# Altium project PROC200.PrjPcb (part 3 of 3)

## Sheet PROC200_EVM_Hardware.SchDoc
size 431 x 279 mm; Date: Not shown in title block; ApprovedBy: Not shown in title block; CheckedBy: Not shown in title block; Author: Not shown in title block; CompanyName: Not shown in title block; Engineer: Not shown in title block; Organization: Not shown in title block; Address1: Not shown in title block; Address2: Not shown in title block; Address3: Not shown in title block; Address4: Not shown in title block; DocumentNumber: 9; Revision: Use project parameter SCH_Rev; SheetNumber: 14; SheetTotal: 14; PageSetup: Record=PageOptions¦CenterHorizontal=True¦CenterVertical=True¦PrintScale=1.00¦XCorrection=1.00¦YCorrection=1.00¦PrintKind=0¦BorderSize=5000000¦LeftOffset=0¦BottomOffset=0¦Orientation=2¦PaperLength=1000¦PaperWidth=1000¦Scale=100¦PaperSource=15¦PrintQuality=600¦MediaType=1¦DitherType=10¦PaperKind=Letter¦PrintScaleMode=1
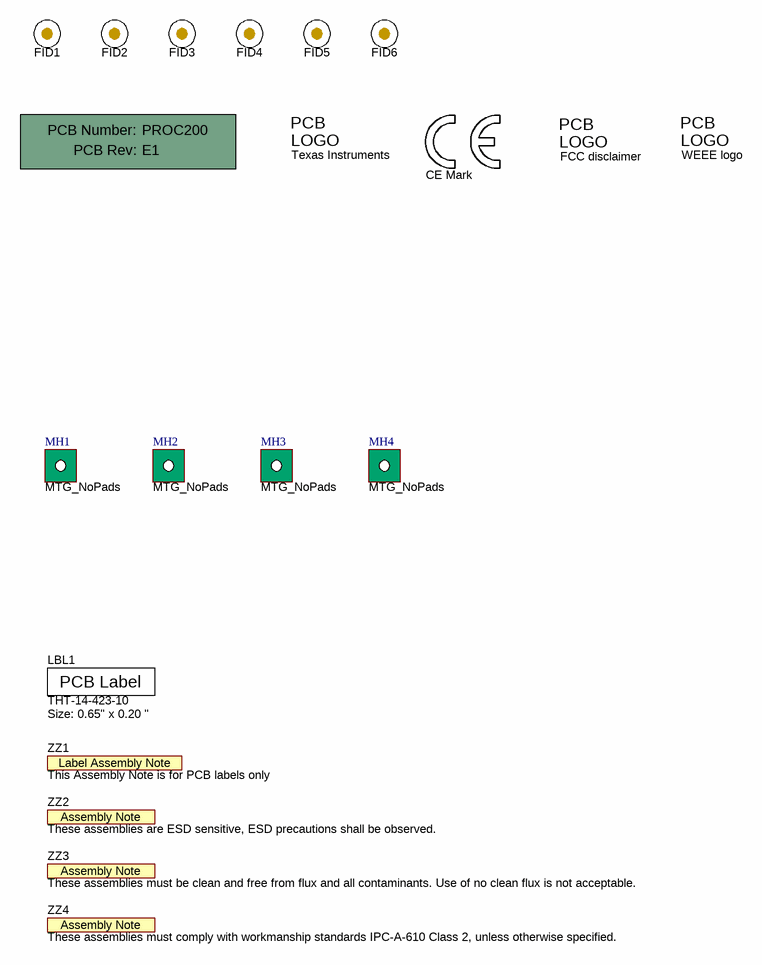
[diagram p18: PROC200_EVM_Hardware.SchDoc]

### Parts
!PCB1  Printed Circuit Board  (value not drawn)  (mechanical)
FID1  Fiducial  [Fiducial10-20]  (value not drawn)
FID2  Fiducial  [Fiducial10-20]  (value not drawn)
FID3  Fiducial  [Fiducial10-20]  (value not drawn)
FID4  Fiducial  [Fiducial10-20]  (value not drawn)
FID5  Fiducial  [Fiducial10-20]  (value not drawn)
FID6  Fiducial  [Fiducial10-20]  (value not drawn)
LBL1  THT-14-423-10  Note: Size: 0.65" x 0.20 "  [Label_650x200]
Logo1  CE Mark  [CE_Mark_5mm]  (no BOM)
Logo2  Texas Instruments  [TI_Stacked_Overlay_Small]  (no BOM)
Logo3  FCC disclaimer  [FCC_disclaimer]  (no BOM)
Logo4  WEEE logo  [WEEE_Minimum]  (no BOM)
MH1  MTG_NoPads  [MTG_159mil]  (no BOM)
MH2  MTG_NoPads  [MTG_159mil]  (no BOM)
MH3  MTG_NoPads  [MTG_159mil]  (no BOM)
MH4  MTG_NoPads  [MTG_159mil]  (no BOM)
ZZ1  This Assembly Note is for PCB labels only  [AssemblyNoteLabel]  (no BOM)
ZZ2  These assemblies are ESD sensitive, ESD precautions shall be observed.  [AssemblyNote]  (no BOM)
ZZ3  These assemblies must be clean and free from flux and all contaminants. Use of no clean flux is not acceptable.  [AssemblyNote]  (no BOM)
ZZ4  These assemblies must comply with workmanship standards IPC-A-610 Class 2, unless otherwise specified.  [AssemblyNote]  (no BOM)

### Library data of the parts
!PCB1 = CMP-0003618-2: Manufacturer: Any; PartNumber: PROC200
FID1-FID6 = CMP-0077181-1: Fiducial mark.  There is nothing to buy or mount.
LBL1 = CMP-0003625-1: Thermal Transfer Printable Labels, 0.650" W x 0.200" H - 10,000 per roll; Manufacturer: Brady
Logo1 = CMP-0074844-1: SymbolCreator: a0412235
Logo2 = CMP-0074838-1: Texas Instrument Corporate Signature; SymbolCreator: a0412235; Lib Reference: TI_Logo; Library Reference: Logo
Logo3 = CMP-0074847-1: FCC_disclaimer
Logo4 = CMP-0074769-3: Manufacturer: Texas Instruments; AEC Category: Q200; CompType: IC
MH1-MH4 = CMP-0078424-2: PCB Mounting Hole, No Pad; Manufacturer: Any; Key: Mounting Hole (non-standard) No Pad
ZZ1 = CMP-0003616-3
ZZ2 = CMP-0077236-1
ZZ3 = CMP-0077237-1
ZZ4 = CMP-0077238-1

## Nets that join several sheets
3V3_LDO2: PROC200_LDO_USB_MICRO-AB (6 pins), PROC200_OSPI_FSI _DAC_Emmulator_Header (12 pins), PROC200_PHY_MUX (31 pins), PROC200_RGMII1_PHY1 (5 pins), PROC200_MII0_PHY2 (5 pins), PROC200_MII1_ADD_ON_CONN (R79.1 R80.1), PROC200_High_Density_conn1_2 (J1.28), PROC200_HSEC_ADC (10 pins), PROC200_180pin_Edge_Connector (C27.2 C28.1 EC1.119 TP2.1)
5V0_LDO3: PROC200_High_Density_conn1_2 (J1.34), PROC200_180pin_Edge_Connector (C29.2 C30.1 EC1.117 TP3.1)
GND: PROC200_LDO_USB_MICRO-AB (32 pins), PROC200_OSPI_FSI _DAC_Emmulator_Header (21 pins), PROC200_PHY_MUX (18 pins), PROC200_RGMII1_PHY1 (33 pins), PROC200_MII0_PHY2 (33 pins), PROC200_MII1_ADD_ON_CONN (23 pins), PROC200_RJ45_1_2 (12 pins), PROC200_High_Density_conn1_2 (19 pins), PROC200_High_Density_conn3 (8 pins), PROC200_HSEC_ADC (29 pins), PROC200_180pin_Edge_Connector (27 pins)
SHIELD5: PROC200_LDO_USB_MICRO-AB (8 pins), PROC200_MII1_ADD_ON_CONN (6 pins)
VDD_ETH_1V1: PROC200_LDO_USB_MICRO-AB (C100.1 TP14.1 U12.1), PROC200_RGMII1_PHY1 (FB3.1), PROC200_MII0_PHY2 (FB1.1)
VDD_ETH_2V5: PROC200_LDO_USB_MICRO-AB (7 pins), PROC200_RGMII1_PHY1 (FB4.1), PROC200_MII0_PHY2 (FB2.1), PROC200_MII1_ADD_ON_CONN (C57.2 C58.1 J6.4 J6.6)
VDDIO_3V3: PROC200_LDO_USB_MICRO-AB (C76.1 R132.2 TP21.1 U11.6), PROC200_RGMII1_PHY1 (17 pins), PROC200_MII0_PHY2 (17 pins), PROC200_MII1_ADD_ON_CONN (C59.2 C60.1 J6.44 J6.46), PROC200_RJ45_1_2 (8 pins)
VMAIN_5V0_IN: PROC200_LDO_USB_MICRO-AB (6 pins), PROC200_High_Density_conn1_2 (J1.18 J1.20 R42.1), PROC200_High_Density_conn3 (J3.27), PROC200_180pin_Edge_Connector (9 pins)
AM26x_ADC0_AIN0/DAC_OUT: PROC200_High_Density_conn1_2 (J1.119), PROC200_HSEC_ADC (R134.1)
AM26x_ADC0_AIN1: PROC200_High_Density_conn1_2 (J1.117), PROC200_HSEC_ADC (R135.1)
AM26x_ADC0_AIN2_P: PROC200_High_Density_conn1_2 (J1.120), PROC200_HSEC_ADC (R136.1)
AM26x_ADC0_AIN3_N: PROC200_High_Density_conn1_2 (J1.118), PROC200_HSEC_ADC (R137.1)
AM26x_ADC0_AIN4_P: PROC200_High_Density_conn1_2 (J1.115), PROC200_HSEC_ADC (R138.1)
AM26x_ADC0_AIN5_N: PROC200_High_Density_conn1_2 (J1.113), PROC200_HSEC_ADC (R139.1)
AM26x_ADC1_AIN0_P: PROC200_High_Density_conn1_2 (J1.116), PROC200_HSEC_ADC (R140.1)
AM26x_ADC1_AIN1_N: PROC200_High_Density_conn1_2 (J1.114), PROC200_HSEC_ADC (R141.1)
AM26x_ADC1_AIN2_P: PROC200_High_Density_conn1_2 (J1.111), PROC200_HSEC_ADC (R142.1)
AM26x_ADC1_AIN3_N: PROC200_High_Density_conn1_2 (J1.109), PROC200_HSEC_ADC (R143.1)
AM26x_ADC1_AIN4: PROC200_High_Density_conn1_2 (J1.112), PROC200_HSEC_ADC (R144.1)
AM26x_ADC1_AIN5: PROC200_High_Density_conn1_2 (J1.110), PROC200_HSEC_ADC (R145.1)
AM26x_ADC2_AIN0_P: PROC200_High_Density_conn1_2 (J1.107), PROC200_HSEC_ADC (R146.1)
AM26x_ADC2_AIN1_N: PROC200_High_Density_conn1_2 (J1.105), PROC200_HSEC_ADC (R147.1)
AM26x_ADC2_AIN2_P: PROC200_High_Density_conn1_2 (J1.108), PROC200_HSEC_ADC (R148.1)
AM26x_ADC2_AIN3_N: PROC200_High_Density_conn1_2 (J1.106), PROC200_HSEC_ADC (R149.1)
AM26x_ADC2_AIN4: PROC200_High_Density_conn1_2 (J1.103), PROC200_HSEC_ADC (R150.1)
AM26x_ADC2_AIN5: PROC200_High_Density_conn1_2 (J1.101), PROC200_HSEC_ADC (R151.1)
AM26x_ADC_CAL0: PROC200_High_Density_conn1_2 (J1.92), PROC200_HSEC_ADC (R152.1)
AM26x_EPWM0_A: PROC200_High_Density_conn1_2 (J1.15), PROC200_180pin_Edge_Connector (EC1.49)
AM26x_EPWM0_B: PROC200_High_Density_conn1_2 (J1.13), PROC200_180pin_Edge_Connector (EC1.51)
AM26x_EPWM1_A: PROC200_High_Density_conn1_2 (J1.11), PROC200_180pin_Edge_Connector (EC1.53)
AM26x_EPWM1_B: PROC200_High_Density_conn1_2 (J1.9), PROC200_180pin_Edge_Connector (EC1.55)
AM26x_EPWM2_A: PROC200_High_Density_conn1_2 (J1.7), PROC200_180pin_Edge_Connector (EC1.50)
AM26x_EPWM2_B: PROC200_High_Density_conn1_2 (J1.5), PROC200_180pin_Edge_Connector (EC1.52)
AM26x_EPWM3_A: PROC200_High_Density_conn1_2 (J1.3), PROC200_180pin_Edge_Connector (EC1.54)
AM26x_EPWM3_B: PROC200_High_Density_conn1_2 (J1.1), PROC200_180pin_Edge_Connector (EC1.56)
AM26x_EPWM4_A: PROC200_High_Density_conn1_2 (J1.16), PROC200_180pin_Edge_Connector (EC1.57)
AM26x_EPWM4_B: PROC200_High_Density_conn1_2 (J1.14), PROC200_180pin_Edge_Connector (EC1.59)
AM26x_EPWM5_A: PROC200_High_Density_conn1_2 (J1.12), PROC200_180pin_Edge_Connector (EC1.61)
AM26x_EPWM5_B: PROC200_High_Density_conn1_2 (J1.10), PROC200_180pin_Edge_Connector (EC1.63)
AM26x_EPWM6_A: PROC200_High_Density_conn1_2 (J1.8), PROC200_180pin_Edge_Connector (EC1.58)
AM26x_EPWM6_B: PROC200_High_Density_conn1_2 (J1.6), PROC200_180pin_Edge_Connector (EC1.60)
AM26x_EPWM7_A: PROC200_OSPI_FSI _DAC_Emmulator_Header (R31.2), PROC200_High_Density_conn1_2 (J1.4), PROC200_180pin_Edge_Connector (EC1.62)
AM26x_EPWM7_B: PROC200_High_Density_conn1_2 (J1.2), PROC200_180pin_Edge_Connector (EC1.64)
AM26x_EPWM8_A: PROC200_High_Density_conn1_2 (J2.58), PROC200_180pin_Edge_Connector (EC2.159)
AM26x_EPWM8_B: PROC200_High_Density_conn1_2 (J2.60), PROC200_180pin_Edge_Connector (EC2.161)
AM26x_EPWM9_A: PROC200_High_Density_conn1_2 (J2.54), PROC200_180pin_Edge_Connector (EC2.163)
AM26x_EPWM9_B: PROC200_High_Density_conn1_2 (J2.56), PROC200_180pin_Edge_Connector (EC2.165)
AM26x_EQEP0_A: PROC200_High_Density_conn1_2 (J1.71), PROC200_180pin_Edge_Connector (EC1.100)
AM26x_EQEP0_B: PROC200_High_Density_conn1_2 (J1.69), PROC200_180pin_Edge_Connector (EC1.102)
AM26x_EQEP0_INDEX: PROC200_High_Density_conn1_2 (J1.65), PROC200_180pin_Edge_Connector (EC1.106)
AM26x_EQEP0_STROBE: PROC200_High_Density_conn1_2 (J1.67), PROC200_180pin_Edge_Connector (EC1.104)
AM26x_FSITX0_CLK: PROC200_OSPI_FSI _DAC_Emmulator_Header (J8.7), PROC200_High_Density_conn1_2 (J1.49)
AM26x_FSITX0_DATA0: PROC200_OSPI_FSI _DAC_Emmulator_Header (J8.5), PROC200_High_Density_conn1_2 (J1.53)
AM26x_FSITX0_DATA1: PROC200_OSPI_FSI _DAC_Emmulator_Header (J8.6), PROC200_High_Density_conn1_2 (J1.51)
AM26x_GPIO15: PROC200_High_Density_conn3 (J3.57), PROC200_180pin_Edge_Connector (EC1.81)
AM26x_GPIO81: PROC200_High_Density_conn3 (J3.72), PROC200_180pin_Edge_Connector (EC1.96)
AM26x_I2C2_SCL: PROC200_High_Density_conn1_2 (J1.61), PROC200_180pin_Edge_Connector (EC1.87)
AM26x_I2C2_SDA: PROC200_High_Density_conn1_2 (J1.63), PROC200_180pin_Edge_Connector (EC1.85)
AM26x_LIN1_RXD: PROC200_High_Density_conn1_2 (J1.37), PROC200_180pin_Edge_Connector (EC1.76)
AM26x_LIN1_TXD: PROC200_High_Density_conn1_2 (J1.35), PROC200_180pin_Edge_Connector (EC1.78)
AM26x_MCAN0_RX: PROC200_High_Density_conn1_2 (J1.38), PROC200_180pin_Edge_Connector (EC1.80)
AM26x_MCAN0_TX: PROC200_High_Density_conn1_2 (J1.36), PROC200_180pin_Edge_Connector (EC1.82)
AM26x_MCAN1_RX: PROC200_High_Density_conn3 (J3.56), PROC200_180pin_Edge_Connector (EC1.94)
AM26x_MCAN1_TX: PROC200_High_Density_conn3 (J3.54), PROC200_180pin_Edge_Connector (EC1.95)
AM26x_SDFM0_CLK0: PROC200_High_Density_conn1_2 (J1.54), PROC200_180pin_Edge_Connector (EC1.72)
AM26x_SDFM0_CLK3: PROC200_High_Density_conn1_2 (J1.46), PROC200_180pin_Edge_Connector (EC1.109)
AM26x_SDFM0_D0: PROC200_High_Density_conn1_2 (J1.60), PROC200_180pin_Edge_Connector (EC1.91)
AM26x_SDFM0_D1: PROC200_High_Density_conn1_2 (J1.58), PROC200_180pin_Edge_Connector (EC1.99)
AM26x_SDFM0_D2: PROC200_High_Density_conn1_2 (J1.56), PROC200_180pin_Edge_Connector (EC1.103)
AM26x_SDFM0_D3: PROC200_High_Density_conn1_2 (J1.50), PROC200_180pin_Edge_Connector (EC1.107)
AM26x_SPI0_CLK: PROC200_High_Density_conn1_2 (J2.34), PROC200_180pin_Edge_Connector (EC1.71)
AM26x_SPI0_CS0: PROC200_High_Density_conn1_2 (J2.36), PROC200_180pin_Edge_Connector (EC1.73)
AM26x_SPI0_D0: PROC200_High_Density_conn1_2 (J2.32), PROC200_180pin_Edge_Connector (EC1.69)
AM26x_SPI0_D1: PROC200_High_Density_conn1_2 (J2.30), PROC200_180pin_Edge_Connector (EC1.67)
AM26x_SPI3_CLK: PROC200_OSPI_FSI _DAC_Emmulator_Header (J4.13), PROC200_High_Density_conn1_2 (J1.41), PROC200_180pin_Edge_Connector (EC2.168)
AM26x_SPI3_CS0: PROC200_OSPI_FSI _DAC_Emmulator_Header (J4.16), PROC200_High_Density_conn1_2 (J1.39), PROC200_180pin_Edge_Connector (EC2.170)
AM26x_SPI3_D0: PROC200_OSPI_FSI _DAC_Emmulator_Header (J4.14), PROC200_High_Density_conn1_2 (J1.45), PROC200_180pin_Edge_Connector (EC2.164)
AM26x_SPI3_D1: PROC200_OSPI_FSI _DAC_Emmulator_Header (J4.15), PROC200_High_Density_conn1_2 (J1.43), PROC200_180pin_Edge_Connector (EC2.166)
AM26x_UART0_RXD: PROC200_OSPI_FSI _DAC_Emmulator_Header (J4.9), PROC200_High_Density_conn1_2 (J1.33), PROC200_180pin_Edge_Connector (EC1.86)
AM26x_UART0_TXD: PROC200_OSPI_FSI _DAC_Emmulator_Header (J4.10), PROC200_High_Density_conn1_2 (J1.31), PROC200_180pin_Edge_Connector (EC1.88)
AM26x_USB0_DM: PROC200_LDO_USB_MICRO-AB (L1.3 R92.1 R93.1), PROC200_High_Density_conn1_2 (J2.40)
AM26x_USB0_DP: PROC200_LDO_USB_MICRO-AB (L1.2 R90.1 R92.2), PROC200_High_Density_conn1_2 (J2.38)
AM26x_USB0_DRVVBUS: PROC200_LDO_USB_MICRO-AB (SW1.1), PROC200_High_Density_conn1_2 (J2.26)
AM26x_VREFHI1: PROC200_High_Density_conn1_2 (J1.85), PROC200_180pin_Edge_Connector (R154.2 R155.1 TP18.1)
AM26x_VREFLO: PROC200_High_Density_conn1_2 (J1.87), PROC200_180pin_Edge_Connector (EC1.43)
DAC_TCK: PROC200_High_Density_conn1_2 (J1.22 R158.2), PROC200_180pin_Edge_Connector (EC1.5)
DAC_TDI: PROC200_High_Density_conn1_2 (J1.19 R156.2), PROC200_180pin_Edge_Connector (EC1.8)
DAC_TDO: PROC200_High_Density_conn1_2 (J1.21 R157.2), PROC200_180pin_Edge_Connector (EC1.6)
DAC_TMS: PROC200_High_Density_conn1_2 (J1.24 R161.2), PROC200_180pin_Edge_Connector (EC1.3)
EXT_VMON2: PROC200_MII1_ADD_ON_CONN (J6.2 TP11.1), PROC200_High_Density_conn3 (J3.59)
HDR_DAC_TCK: PROC200_OSPI_FSI _DAC_Emmulator_Header (J4.4), PROC200_High_Density_conn1_2 (R158.1)
HDR_DAC_TDI: PROC200_OSPI_FSI _DAC_Emmulator_Header (J4.5), PROC200_High_Density_conn1_2 (R156.1)
HDR_DAC_TDO: PROC200_OSPI_FSI _DAC_Emmulator_Header (J4.6), PROC200_High_Density_conn1_2 (R157.1)
HDR_DAC_TMS: PROC200_OSPI_FSI _DAC_Emmulator_Header (J4.3), PROC200_High_Density_conn1_2 (R161.1)
HDR_FSIRX0_CLK: PROC200_OSPI_FSI _DAC_Emmulator_Header (J8.3), PROC200_High_Density_conn1_2 (R39.1)
HDR_FSIRX0_DATA0: PROC200_OSPI_FSI _DAC_Emmulator_Header (J8.1), PROC200_High_Density_conn1_2 (R126.1)
HDR_FSIRX0_DATA1: PROC200_OSPI_FSI _DAC_Emmulator_Header (J8.2), PROC200_High_Density_conn1_2 (R41.1)
HSEC_ADC0_AIN0/DAC_OUT: PROC200_HSEC_ADC (C79.2 R134.2 U3.1), PROC200_180pin_Edge_Connector (EC1.9)
HSEC_ADC0_AIN1: PROC200_HSEC_ADC (C62.2 R135.2 U3.2), PROC200_180pin_Edge_Connector (EC1.11)
HSEC_ADC0_AIN2_P: PROC200_HSEC_ADC (C80.2 R136.2 U3.5), PROC200_180pin_Edge_Connector (EC1.15)
HSEC_ADC0_AIN3_N: PROC200_HSEC_ADC (C63.2 R137.2 U3.4), PROC200_180pin_Edge_Connector (EC1.17)
HSEC_ADC0_AIN4_P: PROC200_HSEC_ADC (C81.2 R138.2 U4.2), PROC200_180pin_Edge_Connector (EC1.21)
HSEC_ADC0_AIN5_N: PROC200_HSEC_ADC (C64.2 R139.2 U4.1), PROC200_180pin_Edge_Connector (EC1.23)
HSEC_ADC1_AIN0_P: PROC200_HSEC_ADC (C82.2 R140.2 U4.4), PROC200_180pin_Edge_Connector (EC1.12)
HSEC_ADC1_AIN1_N: PROC200_HSEC_ADC (C65.2 R141.2 U4.5), PROC200_180pin_Edge_Connector (EC1.14)
HSEC_ADC1_AIN2_P: PROC200_HSEC_ADC (C83.2 R142.2 U5.1), PROC200_180pin_Edge_Connector (EC1.18)
HSEC_ADC1_AIN3_N: PROC200_HSEC_ADC (C66.2 R143.2 U5.2), PROC200_180pin_Edge_Connector (EC1.20)
HSEC_ADC1_AIN4: PROC200_HSEC_ADC (C84.2 R144.2 U6.1), PROC200_180pin_Edge_Connector (EC1.24)
HSEC_ADC1_AIN5: PROC200_HSEC_ADC (C67.2 R145.2 U6.2), PROC200_180pin_Edge_Connector (EC1.26)
HSEC_ADC2_AIN0_P: PROC200_HSEC_ADC (C85.2 R146.2 U6.5), PROC200_180pin_Edge_Connector (EC1.25)
HSEC_ADC2_AIN1_N: PROC200_HSEC_ADC (C68.2 R147.2 U6.4), PROC200_180pin_Edge_Connector (EC1.27)
HSEC_ADC2_AIN2_P: PROC200_HSEC_ADC (C86.2 R148.2 U5.5), PROC200_180pin_Edge_Connector (EC1.31)
HSEC_ADC2_AIN3_N: PROC200_HSEC_ADC (C69.2 R149.2 U5.4), PROC200_180pin_Edge_Connector (EC1.33)
HSEC_ADC2_AIN4: PROC200_HSEC_ADC (C87.2 R150.2 U7.1), PROC200_180pin_Edge_Connector (EC1.37)
HSEC_ADC2_AIN5: PROC200_HSEC_ADC (C70.2 R151.2 U7.2), PROC200_180pin_Edge_Connector (EC1.39)
HSEC_ADC_CAL0: PROC200_HSEC_ADC (C94.2 R152.2 U7.4), PROC200_180pin_Edge_Connector (EC1.28)
HSEC_FSIRX0_CLK: PROC200_High_Density_conn1_2 (R40.1), PROC200_180pin_Edge_Connector (EC1.79)
HSEC_FSIRX0_DATA0: PROC200_High_Density_conn1_2 (R127.1), PROC200_180pin_Edge_Connector (EC1.75)
HSEC_FSIRX0_DATA1: PROC200_High_Density_conn1_2 (R125.1), PROC200_180pin_Edge_Connector (EC1.77)
HSEC_ICSSM_MII0_COL: PROC200_PHY_MUX (U16.24), PROC200_180pin_Edge_Connector (EC1.110)
HSEC_ICSSM_MII0_CRS: PROC200_PHY_MUX (U16.22), PROC200_180pin_Edge_Connector (EC2.121)
HSEC_ICSSM_MII0_RX_DV: PROC200_PHY_MUX (U16.33), PROC200_180pin_Edge_Connector (EC2.124)
HSEC_ICSSM_MII0_RXCLK: PROC200_PHY_MUX (U16.28), PROC200_180pin_Edge_Connector (EC2.123)
HSEC_ICSSM_MII0_RXD0: PROC200_PHY_MUX (U16.42), PROC200_180pin_Edge_Connector (EC2.125)
HSEC_ICSSM_MII0_RXD1: PROC200_PHY_MUX (U16.40), PROC200_180pin_Edge_Connector (EC2.126)
HSEC_ICSSM_MII0_RXD2: PROC200_PHY_MUX (U16.37), PROC200_180pin_Edge_Connector (EC2.127)
HSEC_ICSSM_MII0_RXD3: PROC200_PHY_MUX (U16.35), PROC200_180pin_Edge_Connector (EC2.128)
HSEC_ICSSM_MII0_RXER: PROC200_PHY_MUX (U16.31), PROC200_180pin_Edge_Connector (EC1.108)
HSEC_ICSSM_MII0_RXLINK: PROC200_PHY_MUX (U16.26), PROC200_180pin_Edge_Connector (EC2.122)
HSEC_ICSSM_MII0_TXCLK: PROC200_PHY_MUX (U18.40), PROC200_180pin_Edge_Connector (EC2.129)
HSEC_ICSSM_MII0_TXD0: PROC200_PHY_MUX (U18.37), PROC200_180pin_Edge_Connector (EC2.131)
HSEC_ICSSM_MII0_TXD1: PROC200_PHY_MUX (U18.35), PROC200_180pin_Edge_Connector (EC2.132)
HSEC_ICSSM_MII0_TXD2: PROC200_PHY_MUX (U18.33), PROC200_180pin_Edge_Connector (EC2.133)
HSEC_ICSSM_MII0_TXD3: PROC200_PHY_MUX (U18.31), PROC200_180pin_Edge_Connector (EC2.134)
HSEC_ICSSM_MII0_TXEN: PROC200_PHY_MUX (U18.42), PROC200_180pin_Edge_Connector (EC2.130)
HSEC_ICSSM_MII1_COL: PROC200_PHY_MUX (U17.24), PROC200_180pin_Edge_Connector (EC2.138)
HSEC_ICSSM_MII1_CRS: PROC200_PHY_MUX (U17.22), PROC200_180pin_Edge_Connector (EC2.139)
HSEC_ICSSM_MII1_RX_DV: PROC200_PHY_MUX (U17.33), PROC200_180pin_Edge_Connector (EC2.142)
HSEC_ICSSM_MII1_RXCLK: PROC200_PHY_MUX (U17.28), PROC200_180pin_Edge_Connector (EC2.141)
HSEC_ICSSM_MII1_RXD0: PROC200_PHY_MUX (U17.42), PROC200_180pin_Edge_Connector (EC2.143)
HSEC_ICSSM_MII1_RXD1: PROC200_PHY_MUX (U17.40), PROC200_180pin_Edge_Connector (EC2.144)
HSEC_ICSSM_MII1_RXD2: PROC200_PHY_MUX (U17.37), PROC200_180pin_Edge_Connector (EC2.145)
HSEC_ICSSM_MII1_RXD3: PROC200_PHY_MUX (U17.35), PROC200_180pin_Edge_Connector (EC2.146)
HSEC_ICSSM_MII1_RXER: PROC200_PHY_MUX (U17.31), PROC200_180pin_Edge_Connector (EC2.137)
HSEC_ICSSM_MII1_RXLINK: PROC200_PHY_MUX (U17.26), PROC200_180pin_Edge_Connector (EC2.140)
HSEC_ICSSM_MII1_TXCLK: PROC200_PHY_MUX (U18.18), PROC200_180pin_Edge_Connector (EC2.147)
HSEC_ICSSM_MII1_TXD0: PROC200_PHY_MUX (U18.28), PROC200_180pin_Edge_Connector (EC2.149)
HSEC_ICSSM_MII1_TXD1: PROC200_PHY_MUX (U18.26), PROC200_180pin_Edge_Connector (EC2.150)
HSEC_ICSSM_MII1_TXD2: PROC200_PHY_MUX (U18.24), PROC200_180pin_Edge_Connector (EC2.151)
HSEC_ICSSM_MII1_TXD3: PROC200_PHY_MUX (U18.22), PROC200_180pin_Edge_Connector (EC2.152)
HSEC_ICSSM_MII1_TXEN: PROC200_PHY_MUX (U18.20), PROC200_180pin_Edge_Connector (EC2.148)
ICSSM_MII0_RX_DV: PROC200_PHY_MUX (U16.34), PROC200_MII0_PHY2 (R11.1 R20.2 U1.38)
ICSSM_MII0_RXCLK: PROC200_PHY_MUX (U16.29), PROC200_MII0_PHY2 (R4.1)
ICSSM_MII0_RXD0: PROC200_PHY_MUX (U16.41), PROC200_MII0_PHY2 (R6.1 R15.2 U1.33)
ICSSM_MII0_RXD1: PROC200_PHY_MUX (U16.39), PROC200_MII0_PHY2 (R7.1 R16.2 U1.34)
ICSSM_MII0_RXD2: PROC200_PHY_MUX (U16.38), PROC200_MII0_PHY2 (R12.1 R21.2 U1.35)
ICSSM_MII0_RXD3: PROC200_PHY_MUX (U16.36), PROC200_MII0_PHY2 (R13.1 R22.2 U1.36)
ICSSM_MII0_RXER: PROC200_PHY_MUX (U16.32), PROC200_MII0_PHY2 (R3.2 R9.1 R18.2), PROC200_RJ45_1_2 (R119.1)
ICSSM_MII0_RXLINK: PROC200_PHY_MUX (U16.27), PROC200_MII0_PHY2 (R8.1 R17.2 U1.47), PROC200_RJ45_1_2 (R116.1)
ICSSM_MII0_TXCLK: PROC200_PHY_MUX (U18.39), PROC200_MII0_PHY2 (R1.1)
ICSSM_MII0_TXD0: PROC200_PHY_MUX (U18.38), PROC200_MII0_PHY2 (U1.28)
ICSSM_MII0_TXD1: PROC200_PHY_MUX (U18.36), PROC200_MII0_PHY2 (U1.27)
ICSSM_MII0_TXD2: PROC200_PHY_MUX (U18.34), PROC200_MII0_PHY2 (U1.26)
ICSSM_MII0_TXD3: PROC200_PHY_MUX (U18.32), PROC200_MII0_PHY2 (U1.25)
ICSSM_MII0_TXEN: PROC200_PHY_MUX (U18.41), PROC200_MII0_PHY2 (U1.37)
ICSSM_MII1_COL: PROC200_PHY_MUX (U17.25), PROC200_MII1_ADD_ON_CONN (J6.14)
ICSSM_MII1_CRS: PROC200_PHY_MUX (U17.23), PROC200_MII1_ADD_ON_CONN (J6.30)
ICSSM_MII1_RXCLK: PROC200_PHY_MUX (U17.29), PROC200_MII1_ADD_ON_CONN (J6.19)
ICSSM_MII1_RXD0: PROC200_PHY_MUX (U17.41), PROC200_MII1_ADD_ON_CONN (J6.23)
ICSSM_MII1_RXD1: PROC200_PHY_MUX (U17.39), PROC200_MII1_ADD_ON_CONN (J6.25)
ICSSM_MII1_RXD2: PROC200_PHY_MUX (U17.38), PROC200_MII1_ADD_ON_CONN (J6.27)
ICSSM_MII1_RXD3: PROC200_PHY_MUX (U17.36), PROC200_MII1_ADD_ON_CONN (J6.29)
ICSSM_MII1_RXDV: PROC200_PHY_MUX (U17.34), PROC200_MII1_ADD_ON_CONN (J6.45)
ICSSM_MII1_RXER: PROC200_PHY_MUX (U17.32), PROC200_MII1_ADD_ON_CONN (J6.39)
ICSSM_MII1_RXLINK: PROC200_PHY_MUX (U17.27), PROC200_MII1_ADD_ON_CONN (J6.43)
ICSSM_MII1_TXCLK: PROC200_PHY_MUX (R153.2), PROC200_MII1_ADD_ON_CONN (J6.3)
ICSSM_MII1_TXD0: PROC200_PHY_MUX (U18.29), PROC200_MII1_ADD_ON_CONN (J6.7)
ICSSM_MII1_TXD1: PROC200_PHY_MUX (U18.27), PROC200_MII1_ADD_ON_CONN (J6.9)
ICSSM_MII1_TXD2: PROC200_PHY_MUX (U18.25), PROC200_MII1_ADD_ON_CONN (J6.11)
ICSSM_MII1_TXD3: PROC200_PHY_MUX (U18.23), PROC200_MII1_ADD_ON_CONN (J6.13)
ICSSM_MII1_TXEN: PROC200_PHY_MUX (U18.21), PROC200_MII1_ADD_ON_CONN (J6.35)
LED2_2: PROC200_MII0_PHY2 (R10.1 R19.2 U1.45), PROC200_RJ45_1_2 (R120.1)
LED_0: PROC200_RGMII1_PHY1 (R64.1 R73.2 U2.47), PROC200_RJ45_1_2 (R109.1)
LED_2: PROC200_RGMII1_PHY1 (R65.1 R74.2 U2.45), PROC200_RJ45_1_2 (R113.1)
MCU_GPIO63: PROC200_High_Density_conn1_2 (J2.50), PROC200_180pin_Edge_Connector (EC2.167)
MCU_GPIO64: PROC200_High_Density_conn1_2 (J2.52), PROC200_180pin_Edge_Connector (EC2.169)
MCU_GPIO67: PROC200_High_Density_conn1_2 (J2.57), PROC200_180pin_Edge_Connector (EC2.154)
MCU_GPIO68: PROC200_High_Density_conn1_2 (J2.59), PROC200_180pin_Edge_Connector (EC2.156)
MCU_GPIO69: PROC200_High_Density_conn1_2 (J2.53), PROC200_180pin_Edge_Connector (EC2.160)
MCU_GPIO70: PROC200_High_Density_conn1_2 (J2.55), PROC200_180pin_Edge_Connector (EC2.162)
MCU_GPIO74: PROC200_PHY_MUX (R106.1 U19.1), PROC200_High_Density_conn1_2 (J2.25)
MCU_GPIO120: PROC200_High_Density_conn3 (J3.68), PROC200_180pin_Edge_Connector (EC1.70)
MCU_GPIO121: PROC200_High_Density_conn1_2 (J1.70), PROC200_180pin_Edge_Connector (EC1.74)
MCU_GPIO124: PROC200_High_Density_conn1_2 (J1.72), PROC200_180pin_Edge_Connector (EC1.101)
MCU_GPIO126: PROC200_High_Density_conn1_2 (J1.73), PROC200_180pin_Edge_Connector (EC1.105)
MCU_GPIO136: PROC200_High_Density_conn1_2 (J2.23), PROC200_180pin_Edge_Connector (EC2.153)
MCU_GPIO137: PROC200_High_Density_conn1_2 (J2.21), PROC200_180pin_Edge_Connector (EC2.155)
MCU_I2C0_SCL: PROC200_OSPI_FSI _DAC_Emmulator_Header (J4.12), PROC200_MII1_ADD_ON_CONN (J6.40), PROC200_High_Density_conn1_2 (J1.23), PROC200_180pin_Edge_Connector (EC1.93)
MCU_I2C0_SDA: PROC200_OSPI_FSI _DAC_Emmulator_Header (J4.11), PROC200_MII1_ADD_ON_CONN (J6.42), PROC200_High_Density_conn1_2 (J1.25), PROC200_180pin_Edge_Connector (EC1.92)
MCU_PORz: PROC200_OSPI_FSI _DAC_Emmulator_Header (U20.2), PROC200_RGMII1_PHY1 (U9.2), PROC200_MII0_PHY2 (U8.2), PROC200_High_Density_conn1_2 (J1.29), PROC200_180pin_Edge_Connector (EC1.120 TP25.1)
MDIO0_MDIO: PROC200_OSPI_FSI _DAC_Emmulator_Header (R55.1 R56.1), PROC200_High_Density_conn1_2 (J2.19 R162.2)
MII0/MII1_RST: PROC200_MII0_PHY2 (R44.2 U1.43 U8.4), PROC200_MII1_ADD_ON_CONN (J6.12)
MII0_INTn: PROC200_MII0_PHY2 (R5.1 U1.44), PROC200_High_Density_conn1_2 (J1.75)
MII0_MUX_SEL: PROC200_PHY_MUX (5 pins), PROC200_High_Density_conn1_2 (J2.5)
MII1_INTn: PROC200_MII1_ADD_ON_CONN (J6.10 R79.2), PROC200_High_Density_conn3 (J3.66), PROC200_180pin_Edge_Connector (EC1.68)
MII1_MUX_SEL: PROC200_PHY_MUX (5 pins), PROC200_High_Density_conn1_2 (J2.9)
MII_RST#: PROC200_MII0_PHY2 (R43.2 U8.1), PROC200_High_Density_conn3 (J3.101)
MII_RX_ER: PROC200_RGMII1_PHY1 (R66.1 R75.2 U2.46), PROC200_RJ45_1_2 (R111.1), PROC200_High_Density_conn1_2 (J2.15)
MUX_MDIO0_MDC: PROC200_PHY_MUX (R101.1 U19.3), PROC200_High_Density_conn1_2 (R159.1)
MUX_MDIO0_MDIO: PROC200_PHY_MUX (R100.1 U19.7), PROC200_High_Density_conn1_2 (R162.1)
PHY0_25MHZ_CLK: PROC200_MII0_PHY2 (U1.20), PROC200_High_Density_conn3 (J3.117)
PHY1_25MHZ_CLK: PROC200_MII1_ADD_ON_CONN (J6.28), PROC200_High_Density_conn3 (J3.119)
PHY1_MDIO0_MDC: PROC200_RGMII1_PHY1 (U2.42), PROC200_High_Density_conn1_2 (R160.1)
PHY1_MDIO0_MDIO: PROC200_OSPI_FSI _DAC_Emmulator_Header (R56.2), PROC200_RGMII1_PHY1 (U2.41)
PHY1_RGMII1_RD0: PROC200_OSPI_FSI _DAC_Emmulator_Header (R29.2), PROC200_RGMII1_PHY1 (R61.1 R70.2 U2.33)
PHY1_RGMII1_RD1: PROC200_OSPI_FSI _DAC_Emmulator_Header (R32.2), PROC200_RGMII1_PHY1 (R62.1 R71.2 U2.34)
PHY1_RGMII1_RD2: PROC200_OSPI_FSI _DAC_Emmulator_Header (R34.2), PROC200_RGMII1_PHY1 (R68.1 R77.2 U2.35)
PHY1_RGMII1_RD3: PROC200_OSPI_FSI _DAC_Emmulator_Header (R36.2), PROC200_RGMII1_PHY1 (R69.1 R78.2 U2.36)
PHY1_RGMII1_RX_CTL: PROC200_OSPI_FSI _DAC_Emmulator_Header (R27.2), PROC200_RGMII1_PHY1 (R63.1 R72.2 U2.38)
PHY1_RGMII1_RXC: PROC200_OSPI_FSI _DAC_Emmulator_Header (R25.2), PROC200_RGMII1_PHY1 (R59.1)
PHY1_RGMII1_TD0: PROC200_OSPI_FSI _DAC_Emmulator_Header (R48.2), PROC200_RGMII1_PHY1 (U2.28)
PHY1_RGMII1_TD1: PROC200_OSPI_FSI _DAC_Emmulator_Header (R50.2), PROC200_RGMII1_PHY1 (U2.27)
PHY1_RGMII1_TD2: PROC200_OSPI_FSI _DAC_Emmulator_Header (R52.2), PROC200_RGMII1_PHY1 (U2.26)
PHY1_RGMII1_TD3: PROC200_OSPI_FSI _DAC_Emmulator_Header (R54.2), PROC200_RGMII1_PHY1 (U2.25)
PHY1_RGMII1_TX_CTL: PROC200_OSPI_FSI _DAC_Emmulator_Header (R46.2), PROC200_RGMII1_PHY1 (U2.37)
PHY1_RGMII1_TXC: PROC200_OSPI_FSI _DAC_Emmulator_Header (R38.2), PROC200_RGMII1_PHY1 (R57.1)
PMIC_COMP1_IN+: PROC200_High_Density_conn3 (J3.37), PROC200_180pin_Edge_Connector (EC2.175)
PMIC_COMP1_IN-: PROC200_High_Density_conn3 (J3.35), PROC200_180pin_Edge_Connector (EC2.177)
PMIC_COMP2_IN+: PROC200_High_Density_conn3 (J3.33), PROC200_180pin_Edge_Connector (EC2.171)
PMIC_COMP2_IN-: PROC200_High_Density_conn3 (J3.31), PROC200_180pin_Edge_Connector (EC2.173)
PMIC_SAFE_OUT1: PROC200_High_Density_conn1_2 (J1.32), PROC200_180pin_Edge_Connector (EC2.178)
PMIC_SAFE_OUT2: PROC200_High_Density_conn3 (J3.29), PROC200_180pin_Edge_Connector (EC1.113)
PMIC_WAKE2: PROC200_High_Density_conn1_2 (J1.30), PROC200_180pin_Edge_Connector (EC1.114)
PR0_MDIO0_MDC: PROC200_PHY_MUX (R103.1 U19.2), PROC200_MII1_ADD_ON_CONN (J6.20), PROC200_High_Density_conn3 (J3.97), PROC200_180pin_Edge_Connector (EC1.90)
PR0_MDIO0_MDC_ON: PROC200_PHY_MUX (R104.1 U19.4), PROC200_MII0_PHY2 (U1.42)
PR0_MDIO0_MDIO: PROC200_PHY_MUX (R102.1 U19.8), PROC200_MII1_ADD_ON_CONN (J6.22), PROC200_High_Density_conn3 (J3.99), PROC200_180pin_Edge_Connector (EC1.89)
PR0_MDIO0_MDIO_ON: PROC200_PHY_MUX (R105.1 U19.6), PROC200_MII0_PHY2 (U1.41)
PR0_PRU0_GPIO0: PROC200_PHY_MUX (U16.2), PROC200_High_Density_conn3 (J3.102)
PR0_PRU0_GPIO1: PROC200_PHY_MUX (U16.3), PROC200_High_Density_conn3 (J3.104)
PR0_PRU0_GPIO2: PROC200_PHY_MUX (U16.4), PROC200_High_Density_conn3 (J3.106)
PR0_PRU0_GPIO3: PROC200_PHY_MUX (U16.5), PROC200_High_Density_conn3 (J3.108)
PR0_PRU0_GPIO4: PROC200_PHY_MUX (U16.6), PROC200_High_Density_conn3 (J3.113)
PR0_PRU0_GPIO5: PROC200_PHY_MUX (U16.7), PROC200_High_Density_conn3 (J3.111)
PR0_PRU0_GPIO6: PROC200_PHY_MUX (U16.11), PROC200_High_Density_conn3 (J3.100)
PR0_PRU0_GPIO8: PROC200_PHY_MUX (U16.12), PROC200_High_Density_conn3 (J3.87)
PR0_PRU0_GPIO9: PROC200_PHY_MUX (U16.13), PROC200_High_Density_conn3 (J3.105)
PR0_PRU0_GPIO10: PROC200_PHY_MUX (U16.14), PROC200_High_Density_conn3 (J3.109)
PR0_PRU0_GPIO11: PROC200_PHY_MUX (U18.4), PROC200_High_Density_conn3 (J3.114)
PR0_PRU0_GPIO12: PROC200_PHY_MUX (U18.5), PROC200_High_Density_conn3 (J3.116)
PR0_PRU0_GPIO13: PROC200_PHY_MUX (U18.6), PROC200_High_Density_conn3 (J3.118)
PR0_PRU0_GPIO14: PROC200_PHY_MUX (U18.7), PROC200_High_Density_conn3 (J3.120)
PR0_PRU0_GPIO15: PROC200_PHY_MUX (U18.2), PROC200_High_Density_conn3 (J3.115)
PR0_PRU0_GPIO16: PROC200_PHY_MUX (U18.3), PROC200_High_Density_conn3 (J3.112)
PR0_PRU1_GPIO0: PROC200_PHY_MUX (U17.2), PROC200_High_Density_conn3 (J3.78)
PR0_PRU1_GPIO1: PROC200_PHY_MUX (U17.3), PROC200_High_Density_conn3 (J3.80)
PR0_PRU1_GPIO2: PROC200_PHY_MUX (U17.4), PROC200_High_Density_conn3 (J3.82)
PR0_PRU1_GPIO3: PROC200_PHY_MUX (U17.5), PROC200_High_Density_conn3 (J3.84)
PR0_PRU1_GPIO4: PROC200_PHY_MUX (U17.6), PROC200_High_Density_conn3 (J3.93)
PR0_PRU1_GPIO5: PROC200_PHY_MUX (U17.7), PROC200_High_Density_conn3 (J3.95)
PR0_PRU1_GPIO6: PROC200_PHY_MUX (U17.11), PROC200_High_Density_conn3 (J3.76)
PR0_PRU1_GPIO8: PROC200_PHY_MUX (U17.12), PROC200_High_Density_conn3 (J3.89)
PR0_PRU1_GPIO9: PROC200_PHY_MUX (U17.13), PROC200_High_Density_conn3 (J3.85)
PR0_PRU1_GPIO10: PROC200_PHY_MUX (U17.14), PROC200_High_Density_conn3 (J3.83)
PR0_PRU1_GPIO11: PROC200_PHY_MUX (U18.11), PROC200_High_Density_conn3 (J3.90)
PR0_PRU1_GPIO12: PROC200_PHY_MUX (U18.12), PROC200_High_Density_conn3 (J3.92)
PR0_PRU1_GPIO13: PROC200_PHY_MUX (U18.13), PROC200_High_Density_conn3 (J3.94)
PR0_PRU1_GPIO14: PROC200_PHY_MUX (U18.14), PROC200_High_Density_conn3 (J3.96)
PR0_PRU1_GPIO15: PROC200_PHY_MUX (U18.15), PROC200_High_Density_conn3 (J3.91)
PR0_PRU1_GPIO16: PROC200_PHY_MUX (U18.16), PROC200_High_Density_conn3 (J3.88)
RGMII1_ETH1_CLK: PROC200_RGMII1_PHY1 (U2.20), PROC200_High_Density_conn1_2 (J2.1)
RGMII1_INTn: PROC200_RGMII1_PHY1 (R60.1 U2.44), PROC200_High_Density_conn1_2 (J2.7)
RGMII1_RD0: PROC200_OSPI_FSI _DAC_Emmulator_Header (R28.1 R29.1), PROC200_High_Density_conn1_2 (J2.20)
RGMII1_RD1: PROC200_OSPI_FSI _DAC_Emmulator_Header (R30.1 R32.1), PROC200_High_Density_conn1_2 (J2.18)
RGMII1_RD2: PROC200_OSPI_FSI _DAC_Emmulator_Header (R33.1 R34.1), PROC200_High_Density_conn1_2 (J2.16)
RGMII1_RD3: PROC200_OSPI_FSI _DAC_Emmulator_Header (R35.1 R36.1), PROC200_High_Density_conn1_2 (J2.14)
RGMII1_RST: PROC200_RGMII1_PHY1 (R86.2 U9.1), PROC200_High_Density_conn1_2 (J2.11)
RGMII1_RX_CTL: PROC200_OSPI_FSI _DAC_Emmulator_Header (R26.1 R27.1), PROC200_High_Density_conn1_2 (J2.13)
RGMII1_RXC: PROC200_OSPI_FSI _DAC_Emmulator_Header (R24.1 R25.1), PROC200_High_Density_conn1_2 (J2.22)
RGMII1_TD0: PROC200_OSPI_FSI _DAC_Emmulator_Header (R47.1 R48.1), PROC200_High_Density_conn1_2 (J2.8)
RGMII1_TD1: PROC200_OSPI_FSI _DAC_Emmulator_Header (R49.1 R50.1), PROC200_High_Density_conn1_2 (J2.6)
RGMII1_TD2: PROC200_OSPI_FSI _DAC_Emmulator_Header (R51.1 R52.1), PROC200_High_Density_conn1_2 (J2.4)
RGMII1_TD3: PROC200_OSPI_FSI _DAC_Emmulator_Header (R53.1 R54.1), PROC200_High_Density_conn1_2 (J2.2)
RGMII1_TX_CTL: PROC200_OSPI_FSI _DAC_Emmulator_Header (R45.1 R46.1), PROC200_High_Density_conn1_2 (J2.3)
RGMII1_TXC: PROC200_OSPI_FSI _DAC_Emmulator_Header (R37.1 R38.1), PROC200_High_Density_conn1_2 (J2.10)
RJ45_ETH1_D0_N: PROC200_RGMII1_PHY1 (U2.2), PROC200_RJ45_1_2 (J9.10)
RJ45_ETH1_D0_P: PROC200_RGMII1_PHY1 (U2.1), PROC200_RJ45_1_2 (J9.9)
RJ45_ETH1_D1_N: PROC200_RGMII1_PHY1 (U2.5), PROC200_RJ45_1_2 (J9.8)
RJ45_ETH1_D1_P: PROC200_RGMII1_PHY1 (U2.4), PROC200_RJ45_1_2 (J9.7)
RJ45_ETH1_D2_N: PROC200_RGMII1_PHY1 (U2.8), PROC200_RJ45_1_2 (J9.6)
RJ45_ETH1_D2_P: PROC200_RGMII1_PHY1 (U2.7), PROC200_RJ45_1_2 (J9.5)
RJ45_ETH1_D3_N: PROC200_RGMII1_PHY1 (U2.11), PROC200_RJ45_1_2 (J9.4)
RJ45_ETH1_D3_P: PROC200_RGMII1_PHY1 (U2.10), PROC200_RJ45_1_2 (J9.3)
RJ45_ETH2_D0_N: PROC200_MII0_PHY2 (U1.2), PROC200_RJ45_1_2 (J10.10)
RJ45_ETH2_D0_P: PROC200_MII0_PHY2 (U1.1), PROC200_RJ45_1_2 (J10.9)
RJ45_ETH2_D1_N: PROC200_MII0_PHY2 (U1.5), PROC200_RJ45_1_2 (J10.8)
RJ45_ETH2_D1_P: PROC200_MII0_PHY2 (U1.4), PROC200_RJ45_1_2 (J10.7)
RJ45_ETH2_D2_N: PROC200_MII0_PHY2 (U1.8), PROC200_RJ45_1_2 (J10.6)
RJ45_ETH2_D2_P: PROC200_MII0_PHY2 (U1.7), PROC200_RJ45_1_2 (J10.5)
RJ45_ETH2_D3_N: PROC200_MII0_PHY2 (U1.11), PROC200_RJ45_1_2 (J10.4)
RJ45_ETH2_D3_P: PROC200_MII0_PHY2 (U1.10), PROC200_RJ45_1_2 (J10.3)
USB0_VBUS_OC: PROC200_LDO_USB_MICRO-AB (R88.2 U14.3), PROC200_High_Density_conn1_2 (J2.28)

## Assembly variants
001: not fitted C4 C5 C6 C7 C43 C44 C45 C46 C62 C63 C64 C65 C66 C67 C68 C69 C70 C71 C72 C73 C74 C75 C76 C77 C78 C79 C80 C81 C82 C83 C84 C85 FB? FB? R31 R? R? R? R? R? R? R? R? R? R? R? R? R? R? R? R? R? R? R? R? R? R? R? R? R? R? R? R? R? R? R? R? R? R? R? R? R? R? R? R? R? R? R? R? R? R? R? R? R? R? R? R? R? R? R? R? R? R? R? R? R? R?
